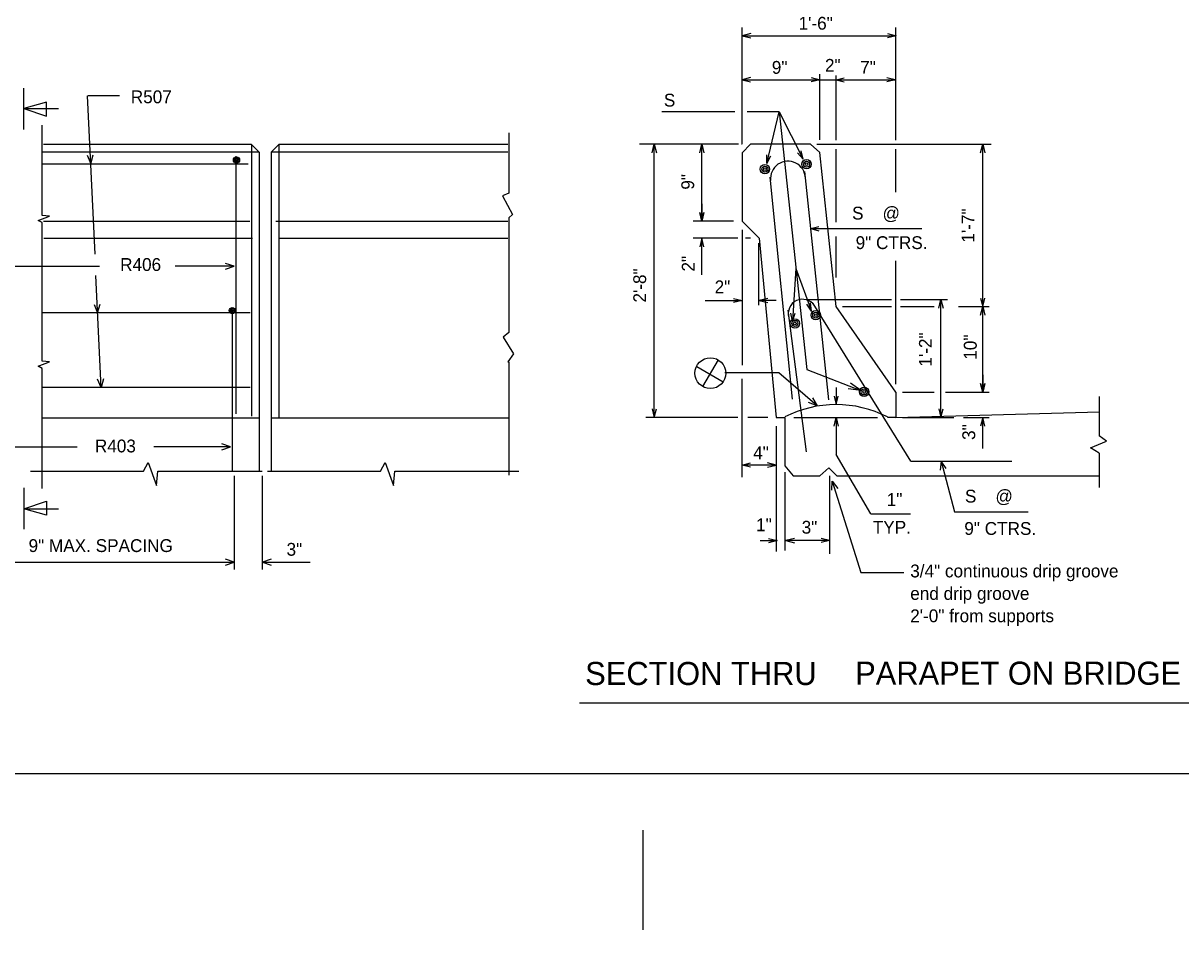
# Model space of a CAD drawing. Extents: x -3.6 to 32.6, y 15.5 to 40.2.
# Drawn here: x 9.24 to 20.52, y 15.75 to 24.58 of the extents above; entities that cross this region are included whole.
import ezdxf

# ---------------------------------------------------------------- set-up
doc = ezdxf.new("R2010")
doc.units = 0
for name, color, linetype in [('Level 1', 7, 'Continuous'), ('Level 2', 7, 'Continuous'), ('Level 37', 7, 'Continuous')]:
    doc.layers.add(name, color=color, linetype=linetype)

msp = doc.modelspace()

# ---------------------------------------------------------------- linework, layer by layer
at = {"layer": 'Level 1'}
msp.add_line((-0.41, 17.273), (30.966, 17.273), dxfattribs=at)
at = {"layer": 'Level 2'}
for p, q in [((16.246, 24.073), (16.246, 24.542)), ((17.746, 24.085), (17.746, 24.542)), ((16.248, 24.461), (17.748, 24.461)), ((16.246, 23.407), (16.246, 24.073)), ((16.246, 24.032), (17.066, 24.032)), ((17.004, 23.448), (17.004, 24.085)), ((17.004, 23.754), (17.004, 24.032)), ((17.066, 24.032), (17.173, 24.032)), ((17.162, 23.442), (17.162, 24.073)), ((17.162, 24.032), (17.242, 24.052)), ((17.162, 24.032), (17.738, 24.032)), ((17.162, 24.032), (17.242, 24.012)), ((17.738, 24.032), (17.658, 24.052)), ((17.738, 24.032), (17.658, 24.012)), ((17.746, 23.442), (17.746, 24.085)), ((9.248, 23.546), (9.248, 23.949)), ((9.468, 23.815), (9.248, 23.751)), ((9.468, 23.678), (9.468, 23.815)), ((9.865, 23.875), (9.938, 22.331)), ((10.179, 23.875), (9.87, 23.875)), ((9.248, 23.751), (9.468, 23.678)), ((9.248, 23.751), (9.585, 23.751)), ((16.175, 23.72), (15.463, 23.72)), ((16.609, 23.72), (16.297, 23.72)), ((16.488, 23.217), (16.609, 23.72)), ((16.609, 23.72), (16.841, 23.257)), ((16.609, 23.72), (16.876, 21.21)), ((13.973, 23.516), (13.973, 22.926)), ((9.437, 23.405), (11.464, 23.405)), ((11.464, 23.401), (11.464, 20.754)), ((11.541, 23.325), (11.464, 23.401)), ((11.656, 23.325), (11.732, 23.401)), ((11.732, 23.405), (13.963, 23.405)), ((11.732, 23.401), (11.732, 20.74)), ((15.77, 23.405), (15.248, 23.405)), ((15.391, 20.741), (15.391, 23.405)), ((16.211, 23.405), (15.77, 23.405)), ((15.854, 22.655), (15.854, 23.405)), ((16.246, 23.405), (16.241, 23.405)), ((16.246, 23.321), (16.329, 23.405)), ((16.912, 23.405), (16.329, 23.405)), ((16.912, 23.405), (17.004, 23.322)), ((16.975, 23.405), (18.674, 23.405)), ((17.162, 22.644), (17.162, 23.356)), ((17.746, 22.937), (17.746, 23.356)), ((18.592, 21.821), (18.592, 23.405)), ((9.427, 23.329), (11.541, 23.329)), ((11.315, 20.778), (11.315, 23.286)), ((11.541, 23.325), (11.541, 20.219)), ((11.656, 23.329), (13.963, 23.329)), ((11.656, 23.325), (11.656, 20.219)), ((16.246, 23.321), (16.246, 22.655)), ((16.488, 23.217), (16.487, 23.299)), ((16.488, 23.217), (16.526, 23.29)), ((16.841, 23.257), (16.787, 23.32)), ((16.841, 23.257), (16.823, 23.338)), ((17.162, 21.821), (17.004, 23.322)), ((11.434, 23.211), (9.425, 23.211)), ((16.856, 23.137), (17.09, 20.914)), ((16.737, 20.92), (16.52, 23.083)), ((16.737, 20.92), (16.52, 23.083)), ((13.973, 22.926), (13.91, 22.9)), ((13.91, 22.9), (14.008, 22.72)), ((15.854, 22.822), (15.854, 22.655)), ((14.008, 22.72), (13.973, 22.685)), ((13.973, 22.685), (13.973, 21.568)), ((9.437, 22.655), (11.45, 22.655)), ((11.702, 22.655), (13.963, 22.655)), ((16.162, 22.655), (15.77, 22.655)), ((16.079, 22.655), (15.77, 22.655)), ((16.246, 22.655), (16.412, 22.488)), ((16.246, 22.571), (16.246, 21.251)), ((16.915, 22.581), (16.995, 22.601)), ((16.915, 22.581), (16.995, 22.561)), ((16.915, 22.581), (17.997, 22.581)), ((9.442, 22.488), (11.476, 22.488)), ((11.728, 22.488), (13.963, 22.488)), ((16.205, 22.488), (15.77, 22.488)), ((15.854, 22.132), (15.854, 22.488)), ((16.329, 22.488), (16.278, 22.488)), ((16.412, 22.488), (16.579, 20.741)), ((17.162, 22.106), (17.162, 22.505)), ((16.407, 22.441), (16.407, 21.834)), ((17.746, 21.065), (17.746, 22.267)), ((8.964, 22.214), (9.984, 22.214)), ((9.999, 21.033), (9.947, 22.125)), ((11.296, 22.214), (10.722, 22.214)), ((16.771, 22.193), (16.737, 21.678)), ((16.771, 22.193), (16.922, 21.776)), ((16.87, 21.89), (17.703, 21.89)), ((17.79, 21.89), (18.247, 21.89)), ((18.184, 20.741), (18.184, 21.89)), ((11.279, 20.219), (11.279, 21.783)), ((15.886, 21.881), (16.246, 21.881)), ((16.58, 21.881), (16.412, 21.881)), ((16.692, 21.787), (16.87, 20.405)), ((16.922, 21.776), (16.876, 21.845)), ((16.922, 21.776), (16.913, 21.858)), ((17.892, 20.317), (16.938, 21.851)), ((17.746, 20.988), (17.162, 21.821)), ((17.225, 21.821), (17.703, 21.821)), ((17.79, 21.821), (18.119, 21.821)), ((18.354, 21.821), (18.655, 21.821)), ((18.592, 20.988), (18.592, 21.821)), ((11.452, 21.761), (9.425, 21.761)), ((16.737, 21.678), (16.722, 21.759)), ((16.737, 21.678), (16.762, 21.756)), ((13.973, 21.568), (13.919, 21.523)), ((13.919, 21.523), (14.018, 21.362)), ((14.018, 21.362), (13.963, 21.282)), ((13.963, 21.282), (13.973, 21.282)), ((13.973, 21.282), (13.973, 20.178)), ((15.804, 21.238), (16.063, 21.089)), ((15.865, 21.044), (16.015, 21.303)), ((16.605, 21.176), (16.077, 21.176)), ((16.246, 20.158), (16.246, 21.118)), ((16.977, 20.854), (16.605, 21.176)), ((16.876, 21.21), (17.403, 21.003)), ((18.592, 21.156), (18.592, 20.988)), ((11.452, 21.033), (9.425, 21.033)), ((17.163, 21.033), (17.163, 20.866)), ((17.403, 21.003), (17.28, 21.019)), ((17.403, 21.003), (17.302, 21.075)), ((17.746, 20.988), (17.746, 20.741)), ((17.808, 20.988), (18.117, 20.988)), ((18.229, 20.988), (18.559, 20.988)), ((18.387, 20.988), (18.655, 20.988)), ((19.725, 20.944), (19.725, 20.562)), ((17.746, 20.741), (19.728, 20.797)), ((9.427, 20.738), (11.541, 20.738)), ((11.656, 20.738), (13.978, 20.738)), ((16.205, 20.741), (15.308, 20.741)), ((16.496, 20.741), (16.302, 20.741)), ((16.579, 20.741), (16.662, 20.741)), ((16.579, 20.658), (16.579, 20.241)), ((16.662, 20.741), (16.662, 20.27)), ((16.75, 20.74), (17.566, 20.74)), ((17.163, 20.74), (17.163, 20.381)), ((17.746, 20.741), (17.662, 20.741)), ((17.808, 20.741), (18.309, 20.741)), ((18.405, 20.741), (18.655, 20.741)), ((18.592, 20.44), (18.592, 20.741)), ((19.799, 20.51), (19.725, 20.562)), ((8.937, 20.455), (9.766, 20.455)), ((11.261, 20.455), (10.513, 20.455)), ((19.643, 20.446), (19.799, 20.51)), ((19.725, 20.394), (19.643, 20.446)), ((17.502, 19.801), (17.163, 20.381)), ((17.892, 20.317), (18.874, 20.317)), ((18.185, 20.317), (18.315, 19.822)), ((19.725, 20.394), (19.725, 20.059)), ((16.579, 20.278), (16.246, 20.278)), ((16.579, 20.241), (16.579, 20.123)), ((16.662, 20.27), (16.744, 20.172)), ((16.662, 20.207), (16.662, 19.446)), ((17.004, 20.172), (17.092, 20.249)), ((17.092, 20.249), (17.168, 20.172)), ((11.297, 20.171), (11.297, 19.261)), ((11.57, 20.171), (11.57, 19.261)), ((16.579, 20.123), (16.579, 19.435)), ((16.744, 20.172), (17.004, 20.172)), ((17.097, 20.174), (17.097, 19.413)), ((17.125, 20.121), (17.402, 19.231)), ((17.168, 20.172), (19.725, 20.172)), ((9.248, 20.057), (9.248, 19.654)), ((9.248, 19.852), (9.468, 19.925)), ((9.468, 19.925), (9.468, 19.788)), ((9.468, 19.788), (9.248, 19.852)), ((9.248, 19.852), (9.585, 19.852)), ((17.502, 19.801), (17.887, 19.801)), ((18.315, 19.822), (19.033, 19.822)), ((16.421, 19.542), (16.589, 19.542)), ((17.097, 19.542), (16.672, 19.542)), ((17.097, 19.542), (17.017, 19.562)), ((17.097, 19.542), (17.017, 19.522)), ((8.929, 19.332), (11.297, 19.332)), ((11.572, 19.332), (12.036, 19.332)), ((17.402, 19.231), (17.824, 19.231)), ((14.661, 17.96), (20.919, 17.96))]:
    msp.add_line(p, q, dxfattribs=at)
for points in [[(16.331, 24.482), (16.248, 24.461), (16.331, 24.44)], [(17.664, 24.482), (17.748, 24.461), (17.664, 24.44)], [(16.329, 24.053), (16.246, 24.032), (16.329, 24.011)], [(16.92, 24.053), (17.004, 24.032), (16.92, 24.011)], [(9.426, 22.09), (9.426, 22.64), (9.385, 22.662), (9.497, 22.704), (9.426, 22.71), (9.426, 23.589)], [(15.37, 23.321), (15.391, 23.405), (15.412, 23.321)], [(15.833, 23.321), (15.854, 23.405), (15.875, 23.321)], [(18.571, 23.321), (18.592, 23.405), (18.613, 23.321)], [(9.865, 23.297), (9.898, 23.214), (9.923, 23.3)], [(15.833, 22.738), (15.854, 22.655), (15.875, 22.738)], [(15.875, 22.738), (15.854, 22.655), (15.833, 22.738)], [(15.875, 22.404), (15.854, 22.488), (15.833, 22.404)], [(11.212, 22.185), (11.296, 22.214), (11.212, 22.243)], [(9.426, 20.048), (9.426, 21.22), (9.385, 21.241), (9.497, 21.283), (9.426, 21.289), (9.426, 22.168)], [(16.162, 21.902), (16.246, 21.881), (16.162, 21.86)], [(16.496, 21.902), (16.412, 21.881), (16.496, 21.86)], [(18.163, 21.807), (18.184, 21.89), (18.205, 21.807)], [(18.571, 21.905), (18.592, 21.821), (18.613, 21.905)], [(9.931, 21.843), (9.965, 21.76), (9.99, 21.846)], [(18.571, 21.737), (18.592, 21.821), (18.613, 21.737)], [(10.024, 21.119), (9.999, 21.033), (9.966, 21.116)], [(18.571, 21.072), (18.592, 20.988), (18.613, 21.072)], [(18.613, 21.072), (18.592, 20.988), (18.571, 21.072)], [(16.932, 20.932), (16.977, 20.854), (16.894, 20.887)], [(17.142, 20.949), (17.163, 20.866), (17.184, 20.949)], [(15.37, 20.825), (15.391, 20.741), (15.412, 20.825)], [(18.163, 20.825), (18.184, 20.741), (18.205, 20.825)], [(17.142, 20.656), (17.163, 20.74), (17.184, 20.656)], [(18.613, 20.657), (18.592, 20.741), (18.571, 20.657)], [(11.177, 20.426), (11.261, 20.455), (11.177, 20.484)], [(18.234, 20.243), (18.185, 20.317), (18.178, 20.228)], [(9.311, 20.219), (10.413, 20.219), (10.457, 20.301), (10.539, 20.077), (10.551, 20.219), (11.569, 20.219)], [(11.622, 20.219), (12.723, 20.219), (12.767, 20.301), (12.849, 20.077), (12.861, 20.219), (14.069, 20.219)], [(16.329, 20.257), (16.246, 20.278), (16.329, 20.299)], [(16.495, 20.257), (16.579, 20.278), (16.495, 20.299)], [(17.122, 20.032), (17.125, 20.121), (17.178, 20.049)], [(16.505, 19.563), (16.589, 19.542), (16.505, 19.521)], [(16.756, 19.563), (16.672, 19.542), (16.756, 19.521)], [(11.213, 19.303), (11.297, 19.332), (11.213, 19.361)], [(11.656, 19.361), (11.572, 19.332), (11.656, 19.303)]]:
    msp.add_lwpolyline(points, dxfattribs=at)
for centre, radius in [((11.319, 23.251), 0.0304), ((11.319, 23.251), 0.0194), ((11.319, 23.251), 0.00907), ((16.875, 23.209), 0.0456), ((16.469, 23.161), 0.0456), ((16.469, 23.161), 0.0292), ((16.469, 23.161), 0.0136), ((16.875, 23.209), 0.0292), ((16.875, 23.209), 0.0136), ((11.278, 21.782), 0.0304), ((11.278, 21.782), 0.0194), ((11.278, 21.782), 0.00907), ((16.964, 21.738), 0.0456), ((16.761, 21.658), 0.0456), ((16.761, 21.658), 0.0292), ((16.761, 21.658), 0.0136), ((16.964, 21.738), 0.0292), ((16.964, 21.738), 0.0136), ((15.937, 21.173), 0.15), ((17.435, 20.99), 0.0456), ((17.435, 20.99), 0.0292), ((17.435, 20.99), 0.0136)]:
    msp.add_circle(centre, radius, dxfattribs=at)
for centre, radius, start, end in [((16.693, 23.069), 0.17, 1.4058, 186.5493), ((16.693, 23.069), 0.17, 1.4058, 186.5493), ((16.836, 21.753), 0.14, 33.7212, 196.604), ((17.162, 19.775), 1.092, 62.7558, 117.2442)]:
    msp.add_arc(centre, radius, start, end, dxfattribs=at)
at = {"layer": 'Level 37'}
msp.add_line((15.278, 16.721), (15.278, 15.749), dxfattribs=at)

# ---------------------------------------------------------------- texts
at = {"layer": 'Level 2'}
for s, height, p in [('1\'-6"', 0.125, (16.797, 24.52)), ('9"', 0.125, (16.536, 24.09)), ('2"', 0.125, (17.054, 24.11)), ('7"', 0.125, (17.397, 24.09)), ('R507', 0.125, (10.289, 23.803)), ('S   ', 0.125, (15.484, 23.771)), ('S    @', 0.125, (17.318, 22.67)), ('9" CTRS.', 0.125, (17.353, 22.382)), ('R406', 0.125, (10.185, 22.169)), ('2"', 0.125, (15.979, 21.951)), ('R403', 0.125, (9.939, 20.401)), ('4"', 0.125, (16.354, 20.334)), ('1"', 0.125, (17.656, 19.879)), ('S    @', 0.125, (18.418, 19.912)), ('1"', 0.125, (16.383, 19.633)), ('3"', 0.125, (16.827, 19.609)), ('TYP.', 0.125, (17.52, 19.609)), ('9" CTRS.', 0.125, (18.412, 19.597)), ('9" MAX. SPACING', 0.125, (9.293, 19.43)), ('3"', 0.125, (11.807, 19.394)), ('3/4" continuous drip groove ', 0.125, (17.885, 19.183)), ('end drip groove ', 0.125, (17.885, 18.964)), ('2\'-0" from supports', 0.125, (17.885, 18.746)), ('SECTION THRU', 0.225, (14.717, 18.134)), ('PARAPET ON BRIDGE', 0.225, (17.348, 18.137))]:
    msp.add_text(s, height=height, dxfattribs=at).set_placement(p)
for s, height, p in [('9"', 0.125, (15.779, 22.961)), ('1\'-7"', 0.125, (18.511, 22.445)), ('2"', 0.125, (15.784, 22.163)), ('2\'-8"', 0.125, (15.311, 21.861)), ('1\'-2"', 0.125, (18.095, 21.237)), ('10"', 0.1258, (18.533, 21.303)), ('3"', 0.1258, (18.518, 20.522))]:
    msp.add_text(s, height=height, rotation=90, dxfattribs=at).set_placement(p)

doc.saveas('drawing.dxf')
